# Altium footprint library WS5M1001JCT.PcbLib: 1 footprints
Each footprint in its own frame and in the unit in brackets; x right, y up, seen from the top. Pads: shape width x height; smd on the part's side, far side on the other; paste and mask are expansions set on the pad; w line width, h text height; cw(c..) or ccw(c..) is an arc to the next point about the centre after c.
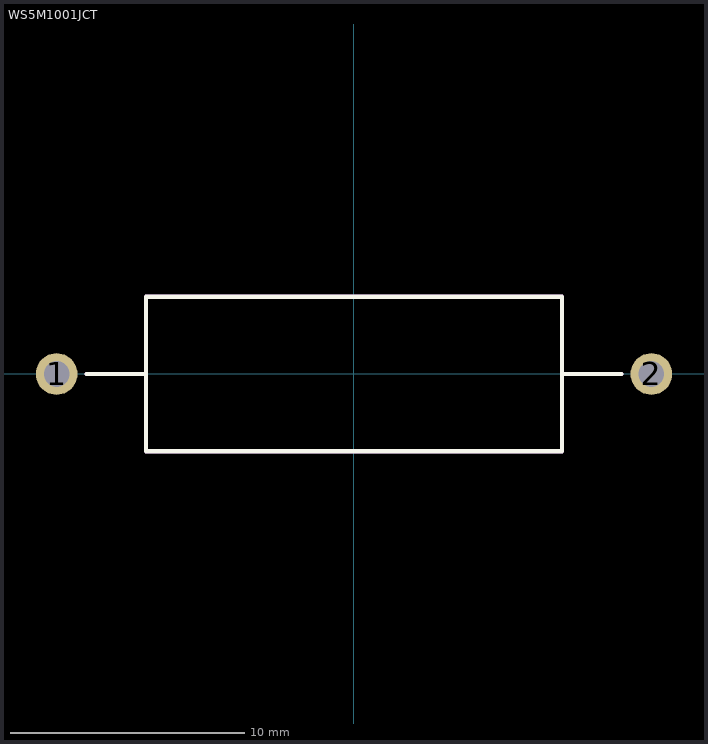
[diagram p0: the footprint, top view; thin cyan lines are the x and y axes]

## WS5M1001JCT [mil] "Bourns P/N WS5M1001JCT"
height 275.59
pads (2):
  round 70 hole 43: 1(-500,0) 2(500,0)
Top Overlay:
  lines w7: -450,0 -350,0 ; 350,0 450,0 ; -350,-130 350,-130 350,130 -350,130 -350,-130
M5 Assembly Top:
  lines w7: -450,0 -350,0 ; 350,0 450,0 ; -350,-130 -350,130 350,130 350,-130 -350,-130
  text ".Designator" at -165.35,-23.62 h72.83
3D body: height 260, standoff 0, extent -350.4,-130 349.6,130
3D body: height 147.47, standoff 112.53, extent 349.99,-17.36 499.99,17.51
3D body: height 130, standoff 0, extent 482.49,-17.47 517.36,17.47
3D body: height 130, standoff 0, extent -517.36,-17.46 -482.5,17.47
3D body: height 147.47, standoff 112.53, extent -500,-17.36 -350,17.51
